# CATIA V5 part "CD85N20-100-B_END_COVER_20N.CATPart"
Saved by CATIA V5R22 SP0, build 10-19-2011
Part number: CD85N20-100-B_END_COVER_20N
Revision: ANY
Definition: UNKNOWN
Nomenclature: CD85N20-100-B_END_COVER_20N
Source: Unknown
Bounding box of the stored display mesh (mm): x -12 to 12, y -12 to 12, z 0 to 35
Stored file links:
  U:\S9A\PER\CAO\Assemblage\Reservoir_Flacon\Verin\Poussoir_2\CD85N20-100-B_END_COVER_20N.CATPart
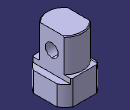
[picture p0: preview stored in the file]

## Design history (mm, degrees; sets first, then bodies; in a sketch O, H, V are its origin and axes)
Body1 "E-EXTEND" (main body)
  Solid1: solid without history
